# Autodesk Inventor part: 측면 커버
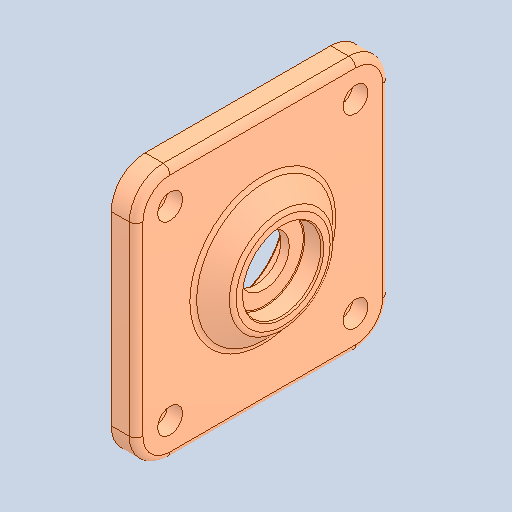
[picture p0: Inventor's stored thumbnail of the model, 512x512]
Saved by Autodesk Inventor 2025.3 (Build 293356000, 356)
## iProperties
Created: 2026-01
Part Number: 측면 커버
Material: 알루미늄 6061
Document SubType Name: Modeling
Designer: PC-13
Density: 2.7 g/cm^3
Appearance: 기본값
Author: jhkim
Sending System: Autodesk Inventor 2026
Preprocessor: ST-DEVELOPER v20.1
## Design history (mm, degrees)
feature "솔리드1"
node "솔리드2"
